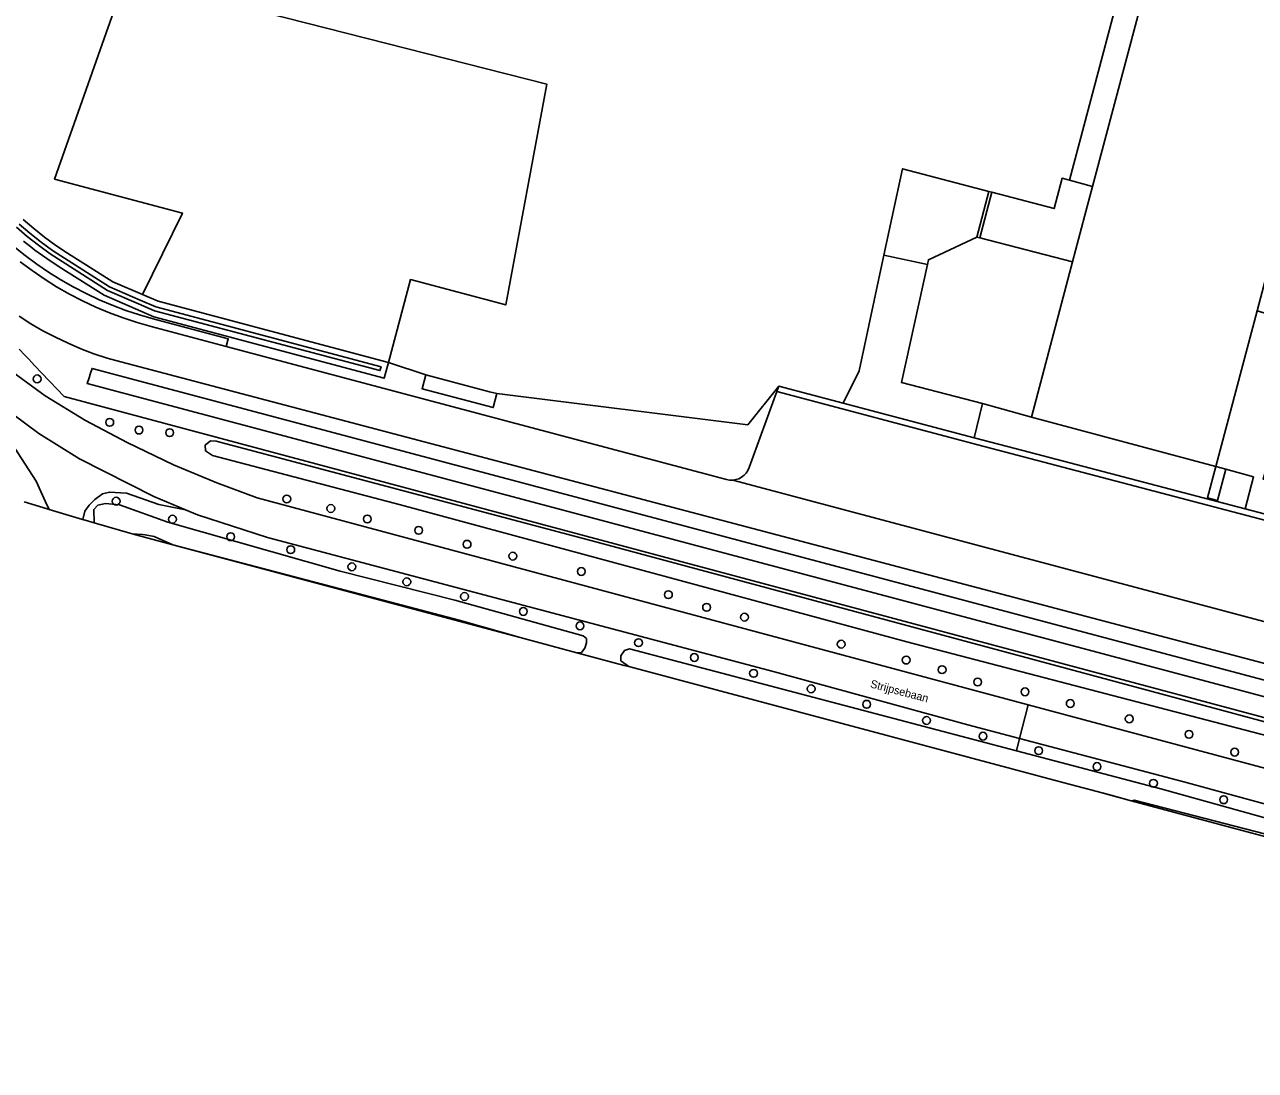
# Model space of a CAD drawing. Extents: x 152881 to 155736, y 382924 to 386919.
# Drawn here: x 154029.1 to 154182.8, y 383095.7 to 383226.3 of the extents above; entities that cross this region are included whole.
import ezdxf

# ---------------------------------------------------------------- set-up
doc = ezdxf.new("R2010")
doc.units = 0
for name, color, linetype in [('IMGEO_Boom', 7, 'Continuous'), ('IMGEO_Bouwland', 7, 'Continuous'), ('IMGEO_Groenvoorziening', 7, 'Continuous'), ('IMGEO_Hek', 7, 'Continuous'), ('IMGEO_Loofbos', 7, 'Continuous'), ('IMGEO_Oever', 7, 'Continuous'), ('IMGEO_Openbare_ruimte_label', 7, 'Continuous'), ('IMGEO_Pand', 7, 'Continuous'), ('IMGEO_Rijbaan_lokaal_gesloten', 7, 'Continuous'), ('IMGEO_Rijbaan_lokaal_halfverhard', 7, 'Continuous'), ('IMGEO_Rijbaan_lokaal_open', 7, 'Continuous'), ('IMGEO_Terreindeel_halfverhard', 7, 'Continuous'), ('IMGEO_Voetpad_gesloten', 7, 'Continuous'), ('IMGEO_Voetpad_op_trap', 7, 'Continuous'), ('IMGEO_Voetpad_open', 7, 'Continuous'), ('IMGEO_Waterloop', 7, 'Continuous')]:
    doc.layers.add(name, color=color, linetype=linetype)

msp = doc.modelspace()

# ---------------------------------------------------------------- linework, layer by layer
at = {"layer": 'IMGEO_Boom'}
for centre in [(154030.64, 383182.09), (154039.71, 383176.67), (154043.37, 383175.7), (154047.19, 383175.38), (154040.51, 383166.82), (154061.83, 383167.1), (154067.33, 383165.91), (154047.55, 383164.57), (154071.89, 383164.59), (154054.82, 383162.38), (154078.3, 383163.18), (154062.32, 383160.76), (154084.35, 383161.44), (154090.06, 383159.96), (154069.96, 383158.63), (154098.63, 383158.04), (154076.82, 383156.75), (154084.03, 383154.92), (154109.5, 383155.14), (154091.38, 383153.05), (154114.27, 383153.56), (154098.46, 383151.25), (154119, 383152.33), (154105.77, 383149.15), (154131.09, 383148.96), (154112.74, 383147.3), (154139.21, 383146.98), (154120.14, 383145.33), (154143.69, 383145.78), (154148.13, 383144.24), (154127.33, 383143.39), (154154.05, 383143.02), (154134.27, 383141.46), (154159.7, 383141.55), (154141.75, 383139.44), (154167.07, 383139.64), (154148.8, 383137.47), (154174.54, 383137.71), (154155.76, 383135.66), (154180.24, 383135.48), (154163.04, 383133.68), (154170.09, 383131.59), (154178.87, 383129.54)]:
    msp.add_circle(centre, 0.489, dxfattribs=at)
at = {"layer": 'IMGEO_Bouwland'}
for points in [[(154047.61, 383161.38), (154045.24, 383162.4), (154044.12, 383162.61), (154043.8, 383162.67), (154042.52, 383162.74)], [(154047.61, 383161.38), (154091.43, 383149.68), (154091.44, 383149.67), (154083.37, 383151.97)], [(154158.96, 383131.64), (154163.05, 383130.55), (154167.3, 383129.41), (154293.39, 383095.74), (154293.17, 383096.29), (154242.24, 383109.96), (154237.53, 383111.19), (154212.83, 383117.82), (154167.69, 383129.5), (154167.32, 383129.42), (154164.49, 383130.18)]]:
    msp.add_lwpolyline(points, close=True, dxfattribs=at)
at = {"layer": 'IMGEO_Groenvoorziening'}
for points in [[(154168.55, 383240.68), (154159.6, 383206.89), (154162.5, 383206.13), (154170.88, 383237.75)], [(154027.75, 383198.63), (154029.15, 383197.5), (154030.59, 383196.43), (154032.07, 383195.42), (154033.6, 383194.46), (154035.16, 383193.57), (154036.75, 383192.74), (154038.38, 383191.98), (154040.03, 383191.28), (154041.71, 383190.65), (154043.42, 383190.08), (154045.15, 383189.58), (154054.52, 383187.09), (154054.27, 383186.13), (154116.76, 383169.53), (154117.14, 383169.46), (154117.53, 383169.45), (154117.92, 383169.51), (154118.29, 383169.63), (154118.64, 383169.82), (154118.95, 383170.05), (154119.22, 383170.33), (154119.44, 383170.66), (154119.6, 383171.01), (154123.05, 383180.52), (154123.29, 383181.18), (154119.41, 383176.34), (154088.07, 383180.25), (154087.61, 383178.51), (154078.72, 383180.87), (154079.18, 383182.61), (154074.52, 383184.16), (154073.99, 383182.18), (154045.21, 383189.83), (154039.02, 383192.53), (154033.38, 383196.1), (154031.86, 383197.11), (154030.37, 383198.18), (154029.85, 383198.59), (154028.94, 383199.31)], [(154028.39, 383185.82), (154029.12, 383185.06), (154029.6, 383184.55), (154030.33, 383183.78), (154034.03, 383179.91), (154286.6, 383112.34), (154296.01, 383110.08), (154295.32, 383113.47), (154294.11, 383119.44), (154294.84, 383119.58), (154294.6, 383120.39), (154289.45, 383119.52), (154288.58, 383119.39), (154286.82, 383119.55), (154285.51, 383119.78), (154041.08, 383184.21), (154039.4, 383184.69), (154037.74, 383185.24), (154036.11, 383185.86), (154034.5, 383186.54), (154032.92, 383187.29), (154031.37, 383188.1), (154029.86, 383188.98), (154028.39, 383189.91)], [(154286.6, 383112.34), (154034.03, 383179.91), (154030.33, 383183.78), (154029.6, 383184.55), (154029.12, 383185.06), (154028.39, 383185.82)], [(154027.14, 383183.27), (154031.63, 383179.99), (154036.69, 383176.91), (154041.89, 383174.16), (154047.67, 383171.36), (154053.09, 383169.1), (154058.11, 383167.26), (154154.46, 383141.41), (154226.11, 383122.18)], [(154029.04, 383166.72), (154031.89, 383165.87), (154032.13, 383165.8), (154031.68, 383166.72), (154030.54, 383169.34), (154025.99, 383176.29)], [(154234.23, 383115.28), (154173.87, 383131.78), (154153.38, 383137.18), (154152.98, 383135.66), (154171.02, 383130.91), (154193.88, 383124.52)]]:
    msp.add_lwpolyline(points, dxfattribs=at)
for points in [[(154094.3, 383218.9), (154041.72, 383232.3), (154032.81, 383207.04), (154048.79, 383202.79), (154043.82, 383192.63), (154045.74, 383191.81), (154074.52, 383184.16), (154077.27, 383194.5), (154089.18, 383191.34)], [(154148.72, 383179), (154154.86, 383177.31), (154160, 383196.72), (154148.4, 383199.7), (154148.01, 383199.8), (154141.99, 383196.97), (154141.86, 383196.39), (154138.61, 383181.66)], [(154189.33, 383188.72), (154183.06, 383190.59), (154177.9, 383171.14), (154179.13, 383170.84), (154182.6, 383169.88), (154181.54, 383165.85), (154207.14, 383159.11), (154208.16, 383163.05), (154197.42, 383165.92), (154197.53, 383166.35), (154196.54, 383166.59), (154196.99, 383168.56), (154197.49, 383170.67), (154198.6, 383170.39), (154201.72, 383182.11), (154212.79, 383179.18), (154214.64, 383178.73), (154215.43, 383181.6), (154198.8, 383186.14), (154194.75, 383166.62), (154183.82, 383169.55)], [(154279.63, 383116.96), (154036.91, 383181.5), (154037.13, 383182.22), (154037.28, 383182.69), (154037.5, 383183.41), (154280.29, 383118.85), (154286.79, 383116), (154285.99, 383114.17)], [(154155.86, 383146.84), (154205.05, 383133.61), (154253.56, 383120.41), (154293.05, 383110), (154292.87, 383108.88), (154253.14, 383118.76), (154206.65, 383131.7), (154155.4, 383145.06), (154139.27, 383149.26), (154076.04, 383166.38), (154052.55, 383172.51), (154051.66, 383173.09), (154051.64, 383173.82), (154052.29, 383174.34), (154052.99, 383174.33), (154099.83, 383161.9)], [(154104.57, 383146.17), (154103.55, 383146.89), (154103.56, 383147.49), (154104, 383148.17), (154104.63, 383148.39), (154152.98, 383135.66), (154153.38, 383137.18), (154146.89, 383138.88), (154122.76, 383145.5), (154059.4, 383162.27), (154050.69, 383165.13), (154049.17, 383165.75), (154045.84, 383166.42), (154041.81, 383167.83), (154039.68, 383167.95), (154038.82, 383167.72), (154037.85, 383167.04), (154037.13, 383166.34), (154036.61, 383165.57), (154036.35, 383164.54), (154037.76, 383164.12), (154037.76, 383164.12), (154037.74, 383165.79), (154038.22, 383166.32), (154039.17, 383166.52), (154040.91, 383166.35), (154046.97, 383164.18), (154068.49, 383158.08), (154082.83, 383154.48), (154098.86, 383150.01), (154099.25, 383149.67), (154099.28, 383149.14), (154099.05, 383148.48), (154098.63, 383147.93), (154098.08, 383147.9), (154103.99, 383146.32)]]:
    msp.add_lwpolyline(points, close=True, dxfattribs=at)
at = {"layer": 'IMGEO_Hek'}
for points in [[(154028.39, 383185.82), (154029.12, 383185.06)], [(154029.12, 383185.06), (154029.6, 383184.55)], [(154029.6, 383184.55), (154030.33, 383183.78)], [(154294.11, 383119.44), (154295.32, 383113.47), (154296.01, 383110.08), (154286.6, 383112.34), (154034.03, 383179.91), (154030.33, 383183.78)]]:
    msp.add_lwpolyline(points, dxfattribs=at)
at = {"layer": 'IMGEO_Loofbos'}
msp.add_lwpolyline([(154028.88, 383201.99), (154030.21, 383200.86), (154031.58, 383199.78), (154032.99, 383198.75), (154034.45, 383197.79), (154040.1, 383194.22), (154043.82, 383192.63), (154048.79, 383202.79), (154032.81, 383207.04), (154041.72, 383232.3), (154094.3, 383218.9), (154089.18, 383191.34), (154077.27, 383194.5), (154074.52, 383184.16), (154079.18, 383182.61), (154087.16, 383180.49), (154088.07, 383180.25), (154119.41, 383176.34), (154123.29, 383181.18), (154131.35, 383179.05), (154133.32, 383183.1), (154136.43, 383197.55), (154138.75, 383208.34), (154149.51, 383205.51), (154149.9, 383205.41), (154157.69, 383203.36), (154158.68, 383207.14), (154159.6, 383206.89), (154168.55, 383240.68)], dxfattribs=at)
at = {"layer": 'IMGEO_Oever'}
for points in [[(154028.38, 383201.43), (154029.73, 383200.28), (154031.13, 383199.18), (154032.57, 383198.14), (154034.04, 383197.16), (154039.68, 383193.59), (154043.52, 383191.91), (154045.48, 383191.07), (154073.6, 383183.61), (154073.47, 383183.12), (154045.32, 383190.6), (154043.32, 383191.46), (154039.44, 383193.15), (154033.77, 383196.74), (154032.28, 383197.73), (154030.83, 383198.78), (154029.41, 383199.89), (154028.05, 383201.06)], [(154028.94, 383199.31), (154029.85, 383198.59), (154030.37, 383198.18), (154031.86, 383197.11), (154033.38, 383196.1), (154039.02, 383192.53), (154045.21, 383189.83), (154073.99, 383182.18), (154074.52, 383184.16), (154045.74, 383191.81), (154043.82, 383192.63), (154040.1, 383194.22), (154034.45, 383197.79), (154032.99, 383198.75), (154031.58, 383199.78), (154030.21, 383200.86), (154028.88, 383201.99)]]:
    msp.add_lwpolyline(points, dxfattribs=at)
at = {"layer": 'IMGEO_Pand'}
msp.add_lwpolyline([(154183.06, 383190.59), (154184.57, 383196.3), (154193.92, 383231.59), (154191.29, 383232.29), (154173.24, 383237.11), (154170.88, 383237.75), (154162.5, 383206.13), (154161.5, 383202.36), (154160, 383196.72), (154154.86, 383177.31), (154177.9, 383171.14)], close=True, dxfattribs=at)
at = {"layer": 'IMGEO_Rijbaan_lokaal_gesloten'}
for points in [[(154241.31, 383136.53), (154117.53, 383169.45), (154117.14, 383169.46), (154116.76, 383169.53), (154054.27, 383186.13), (154044.89, 383188.62), (154043.12, 383189.13), (154041.38, 383189.7), (154039.66, 383190.35), (154037.97, 383191.06), (154036.31, 383191.85), (154034.68, 383192.69), (154033.08, 383193.6), (154031.53, 383194.58), (154030.01, 383195.62), (154028.54, 383196.71)], [(154028.39, 383189.91), (154029.86, 383188.98), (154031.37, 383188.1), (154032.92, 383187.29), (154034.5, 383186.54), (154036.11, 383185.86), (154037.74, 383185.24), (154039.4, 383184.69), (154041.08, 383184.21), (154285.51, 383119.78)]]:
    msp.add_lwpolyline(points, dxfattribs=at)
msp.add_lwpolyline([(154241.02, 383136.72), (154240.78, 383136.97), (154240.61, 383137.26), (154240.5, 383137.59), (154240.46, 383137.93), (154240.51, 383138.27), (154243.08, 383148.93), (154148.16, 383173.85), (154123.05, 383180.52), (154119.6, 383171.01), (154119.44, 383170.66), (154119.22, 383170.33), (154118.95, 383170.05), (154118.64, 383169.82), (154118.29, 383169.63), (154117.92, 383169.51), (154117.53, 383169.45), (154241.31, 383136.53)], close=True, dxfattribs=at)
at = {"layer": 'IMGEO_Rijbaan_lokaal_halfverhard'}
for points in [[(154036.35, 383164.54), (154036.61, 383165.57), (154037.13, 383166.34), (154037.85, 383167.04), (154038.82, 383167.72), (154039.68, 383167.95), (154041.81, 383167.83), (154045.84, 383166.42), (154049.17, 383165.75), (154045.2, 383167.4), (154035.94, 383172.13), (154030.85, 383175.27), (154024.47, 383179.99), (154015.99, 383187.44), (154015.93, 383186.56), (154023.57, 383179.52), (154025.99, 383176.29), (154030.54, 383169.34), (154031.68, 383166.72), (154032.13, 383165.8), (154036.3, 383164.55)], [(154154.46, 383141.41), (154153.38, 383137.18), (154173.87, 383131.78), (154234.23, 383115.28), (154250.05, 383111.69), (154272.97, 383105.01), (154274.12, 383109.53), (154266.39, 383111.73), (154226.11, 383122.18)]]:
    msp.add_lwpolyline(points, close=True, dxfattribs=at)
msp.add_lwpolyline([(154024.47, 383179.99), (154030.85, 383175.27), (154035.94, 383172.13), (154045.2, 383167.4), (154049.17, 383165.75), (154050.69, 383165.13), (154059.4, 383162.27), (154122.76, 383145.5), (154146.89, 383138.88), (154153.38, 383137.18), (154154.46, 383141.41), (154058.11, 383167.26), (154053.09, 383169.1), (154047.67, 383171.36), (154041.89, 383174.16), (154036.69, 383176.91), (154031.63, 383179.99), (154027.14, 383183.27)], dxfattribs=at)
at = {"layer": 'IMGEO_Rijbaan_lokaal_open'}
for points in [[(154149.9, 383205.41), (154149.51, 383205.51), (154148.01, 383199.8), (154148.4, 383199.7)], [(154243.24, 383149.61), (154221.58, 383155.31), (154219.39, 383155.88), (154209.42, 383158.51), (154207.14, 383159.11), (154181.54, 383165.85), (154178.04, 383166.77), (154153.76, 383173.16), (154147.7, 383174.75), (154131.35, 383179.05), (154123.29, 383181.18), (154123.05, 383180.52), (154148.16, 383173.85), (154243.08, 383148.93)]]:
    msp.add_lwpolyline(points, close=True, dxfattribs=at)
at = {"layer": 'IMGEO_Terreindeel_halfverhard'}
msp.add_lwpolyline([(154028.54, 383196.71), (154030.01, 383195.62), (154031.53, 383194.58), (154033.08, 383193.6), (154034.68, 383192.69), (154036.31, 383191.85), (154037.97, 383191.06), (154039.66, 383190.35), (154041.38, 383189.7), (154043.12, 383189.13), (154044.89, 383188.62), (154054.27, 383186.13), (154054.52, 383187.09), (154045.15, 383189.58), (154043.42, 383190.08), (154041.71, 383190.65), (154040.03, 383191.28), (154038.38, 383191.98), (154036.75, 383192.74), (154035.16, 383193.57), (154033.6, 383194.46), (154032.07, 383195.42), (154030.59, 383196.43), (154029.15, 383197.5), (154027.75, 383198.63)], dxfattribs=at)
at = {"layer": 'IMGEO_Voetpad_gesloten'}
for points in [[(154149.51, 383205.51), (154138.75, 383208.34), (154136.43, 383197.55), (154141.86, 383196.39), (154141.99, 383196.97), (154148.01, 383199.8)], [(154162.5, 383206.13), (154159.6, 383206.89), (154158.68, 383207.14), (154157.69, 383203.36), (154149.9, 383205.41), (154148.4, 383199.7), (154160, 383196.72), (154161.5, 383202.36)], [(154178.08, 383166.91), (154176.86, 383167.25), (154177.9, 383171.14), (154154.86, 383177.31), (154148.72, 383179), (154147.7, 383174.75), (154153.76, 383173.16), (154178.04, 383166.77)]]:
    msp.add_lwpolyline(points, close=True, dxfattribs=at)
at = {"layer": 'IMGEO_Voetpad_op_trap'}
msp.add_lwpolyline([(154179.13, 383170.84), (154177.9, 383171.14), (154176.86, 383167.25), (154178.08, 383166.91)], close=True, dxfattribs=at)
at = {"layer": 'IMGEO_Voetpad_open'}
for points in [[(154131.35, 383179.05), (154147.7, 383174.75), (154148.72, 383179), (154138.61, 383181.66), (154141.86, 383196.39), (154136.43, 383197.55), (154133.32, 383183.1)], [(154181.54, 383165.85), (154182.6, 383169.88), (154179.13, 383170.84), (154178.08, 383166.91), (154178.04, 383166.77)]]:
    msp.add_lwpolyline(points, close=True, dxfattribs=at)
at = {"layer": 'IMGEO_Waterloop'}
msp.add_lwpolyline([(154028.05, 383201.06), (154029.41, 383199.89), (154030.83, 383198.78), (154032.28, 383197.73), (154033.77, 383196.74), (154039.44, 383193.15), (154043.32, 383191.46), (154045.32, 383190.6), (154073.47, 383183.12), (154073.6, 383183.61), (154045.48, 383191.07), (154043.52, 383191.91), (154039.68, 383193.59), (154034.04, 383197.16), (154032.57, 383198.14), (154031.13, 383199.18), (154029.73, 383200.28), (154028.38, 383201.43)], dxfattribs=at)
for points in [[(154037.5, 383183.41), (154037.28, 383182.69), (154037.13, 383182.22), (154036.91, 383181.5), (154279.63, 383116.96), (154285.99, 383114.17), (154286.79, 383116), (154280.29, 383118.85)], [(154079.18, 383182.61), (154078.72, 383180.87), (154087.61, 383178.51), (154088.07, 383180.25), (154087.16, 383180.49)], [(154155.86, 383146.84), (154099.83, 383161.9), (154052.99, 383174.33), (154052.29, 383174.34), (154051.64, 383173.82), (154051.66, 383173.09), (154052.55, 383172.51), (154076.04, 383166.38), (154139.27, 383149.26), (154155.4, 383145.06), (154206.65, 383131.7), (154253.14, 383118.76), (154292.87, 383108.88), (154293.05, 383110), (154253.56, 383120.41), (154205.05, 383133.61)], [(154042.52, 383162.74), (154043.8, 383162.67), (154044.12, 383162.61), (154045.24, 383162.4), (154047.61, 383161.38), (154083.37, 383151.97), (154091.44, 383149.67), (154098.08, 383147.9), (154098.08, 383147.9), (154098.63, 383147.93), (154099.05, 383148.48), (154099.28, 383149.14), (154099.25, 383149.67), (154098.86, 383150.01), (154082.83, 383154.48), (154068.49, 383158.08), (154046.97, 383164.18), (154040.91, 383166.35), (154039.17, 383166.52), (154038.22, 383166.32), (154037.74, 383165.79), (154037.76, 383164.12)], [(154158.96, 383131.64), (154164.49, 383130.18), (154167.32, 383129.42), (154167.69, 383129.5), (154212.83, 383117.82), (154237.53, 383111.19), (154238.18, 383111.39), (154238.64, 383112.24), (154238.32, 383112.88), (154215.4, 383118.73), (154193.88, 383124.52), (154171.02, 383130.91), (154152.98, 383135.66), (154104.63, 383148.39), (154104, 383148.17), (154103.56, 383147.49), (154103.55, 383146.89), (154104.57, 383146.17), (154152.4, 383133.39)]]:
    msp.add_lwpolyline(points, close=True, dxfattribs=at)

# ---------------------------------------------------------------- texts
at = {"layer": 'IMGEO_Openbare_ruimte_label'}
msp.add_text('Strijpsebaan', height=1, rotation=345.2273, dxfattribs=at).set_placement((154134.65, 383143.58))

doc.saveas('drawing.dxf')
